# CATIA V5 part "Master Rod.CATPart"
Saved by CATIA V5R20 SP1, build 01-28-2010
Part number: Master Rod
Bounding box of the stored display mesh (mm): x -55.99 to 55.99, y -51.999 to 267.322, z -35 to 35
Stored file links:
  D:\v5_r20\psrt_files_downloaded\c13-catia-v5r20-prt\c13-catia-v5r20-figr-13-41\Part & Asm files\Master Rod.CATPart
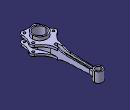
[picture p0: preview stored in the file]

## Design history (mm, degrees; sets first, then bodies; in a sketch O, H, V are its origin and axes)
Body1 (main body)
  Sketch1 on xy-plane, origin (0, 0, 0), H (1, 0, 0), V (0, 1, 0)
    arc A1 centre (0, 0) radius 31.5 from (-26.3425, 17.272) to (26.3425, 17.272) ccw
    arc A2 centre (0, 250) radius 17.5 from (14.7398, 240.5666) to (-14.7398, 240.5666) ccw
    point P1 (0, 250)
    line L1 (9, 220) -> (13, 60)
    point P2 (9, 220)
    point P3 (13, 60)
    arc A3 centre (94.6219, 62.0405) radius 81.6474 from (13, 60) to (26.3425, 17.272) ccw
    point P5 (26.3425, 17.272)
    arc A4 centre (45.4514, 220.9113) radius 36.4628 from (9, 220) to (14.7398, 240.5666) cw
    point P7 (14.7398, 240.5666)
    point P8 (-14.7398, 240.5666)
    point P9 (-9, 220)
    arc A5 centre (-45.4514, 220.9113) radius 36.4628 from (-9, 220) to (-14.7398, 240.5666) ccw
    point P11 (-13, 60)
    line L2 (-9, 220) -> (-13, 60)
    point P12 (-26.3425, 17.272)
    arc A6 centre (-94.6219, 62.0405) radius 81.6474 from (-13, 60) to (-26.3425, 17.272) cw
    radius A1 = 31.5
    radius A2 = 17.5
    distance P1 H = 250
    distance V P3 = 13
    distance P2 V = 9
    distance P1 P2 V = 30
    distance P3 P2 V = 160
    coincidence: P1 V
    tangency: A3 L1, A3 A1, A4 L1, A4 A2
    symmetry: P7 P8 V, P2 P9 V, A4 A5 V, P3 P11 V, L1 L2 V, P5 P12 V, A3 A6 V
  Pad1: profile Sketch1, direction (0, 0, 1), length 21, mirrored extent
  Sketch2 on face of Pad1, origin (0, 0, 21), H (1, 0, 0), V (0, 1, 0)
    point P1 (43, 16)
    point P2 (26, -39)
    arc A1 centre (43, 16) radius 13 from (53.3864, 8.1819) to (49.3111, 27.3653) ccw
    arc A2 centre (26, -39) radius 13 from (22.0235, -51.3769) to (38.9864, -38.4063) ccw
    reference projected line E1 (9, 220) -> (12.2872, 88.5122) from edge of Pad1
    arc A3 centre (84.2647, 90.3117) radius 72 from (49.3111, 27.3653) to (12.2872, 88.5122) cw
    point P5 (49.3111, 27.3653)
    point P6 (12.2872, 88.5122)
    arc A4 centre (110.9113, -35.118) radius 72 from (38.9864, -38.4063) to (53.3864, 8.1819) cw
    point P8 (38.9864, -38.4063)
    point P9 (53.3864, 8.1819)
    point P10 (-12.2872, 88.5122)
    point P11 (-49.3111, 27.3653)
    arc A5 centre (-84.2647, 90.3117) radius 72 from (-49.3111, 27.3653) to (-12.2872, 88.5122) ccw
    point P13 (-53.3864, 8.1819)
    arc A6 centre (-43, 16) radius 13 from (-53.3864, 8.1819) to (-49.3111, 27.3653) cw
    point P15 (-38.9864, -38.4063)
    arc A7 centre (-110.9113, -35.118) radius 72 from (-38.9864, -38.4063) to (-53.3864, 8.1819) ccw
    arc A8 centre (-26, -39) radius 13 from (-22.0235, -51.3769) to (-38.9864, -38.4063) cw
    line L1 (12.2872, 88.5122) -> (-12.2872, 88.5122)
    arc A9 centre (0, -119.9259) radius 72 from (-22.0235, -51.3769) to (22.0235, -51.3769) cw
    distance V P2 = 26
    distance P2 P1 H = 17
    distance P1 P2 V = 55
    distance P2 H = 39
    radius A1 = 13
    radius A2 = 13
    radius A3 = 72
    radius A4 = 72
    radius A9 = 72
    tangency: A3 E1, A3 A1, A4 A1, A4 A2, A9 A8, A9 A2
    symmetry: P6 P10 V, P5 P11 V, A3 A5 V, P9 P13 V, A1 A6 V, P8 P15 V, A4 A7 V, A2 A8 V
    horizontal: L1 H
  Pad2: profile Sketch2, direction (0, 0, -1), length 9
  Mirror1: of Pad2, Sketch2, about xy-plane
  Sketch3 on xy-plane, origin (0, 0, 0), H (1, 0, 0), V (0, 1, 0)
    circle A1 centre (0, 0) radius 31.5
    reference projected arc E1 centre (0, 0) radius 31.5 from (-26.3425, 17.272) to (26.3425, 17.272) ccw from edge of Pad2
    tangency: A1 E1
  Pad3: profile Sketch3, direction (0, 0, 1), length 35, mirrored extent
  Sketch4 on xy-plane, origin (0, 0, 0), H (1, 0, 0), V (0, 1, 0)
    circle A1 centre (0, 0) radius 26
    circle A2 centre (43, 16) radius 5
    circle A3 centre (26, -39) radius 5
    reference projected arc E1 centre (43, 16) radius 13 from (53.3864, 8.1819) to (49.3111, 27.3653) ccw from edge of Pad2
    reference projected arc E2 centre (26, -39) radius 13 from (22.0235, -51.3769) to (38.9864, -38.4063) ccw from edge of Pad2
    circle A4 centre (-26, -39) radius 5
    circle A5 centre (-43, 16) radius 5
    radius A1 = 26
    radius A3 = 5
    radius A2 = 5
    concentricity: A2 E1, A3 E2
    symmetry: A3 A4 V, A2 A5 V
  Pocket1: profile Sketch4, direction (0, 0, -1), length 35, mirrored extent
  Sketch5 on yz-plane, origin (0, 0, 0), H (0, 1, 0), V (0, 0, 1)
    line L1 (123.0834, 12) -> (250, 9)
    point P1 (123.0834, 12)
    point P2 (250, 9)
    arc A1 centre (124.9266, 89.9782) radius 78 from (88.5122, 21) to (123.0834, 12) ccw
    line L2 (88.5122, 21) -> (88.5122, 33.8539)
    line L3 (88.5122, 33.8539) -> (280.7471, 33.8539)
    line L4 (280.7471, 33.8539) -> (280.7471, 8.2732)
    point P8 (280.7471, 8.2732)
    line L5 (280.7471, 8.2732) -> (250, 9)
    distance P1 H = 12
    distance H P2 = 9
    distance V P2 = 250
    radius A1 = 78
    tangency: A1 L1, L5 A1
    vertical: L2 V, L4 V
    horizontal: L3 H
    coincidence: P8 L1
  Pocket2: profile Sketch5, direction (-1, 0, 0), length 35, mirrored extent
  Mirror2: of Pocket2, Sketch5, about xy-plane
  Sketch6 on xy-plane, origin (0, 0, 0), H (1, 0, 0), V (0, 1, 0)
    circle A1 centre (0, 250) radius 17.5
    point P1 (0, 250)
    reference projected arc E1 centre (0, 250) radius 17.5 from (17.5, 250) to (-17.5, 250) ccw from edge of Mirror2
    reference projected arc E2 centre (0, 250) radius 17.5 from (17.5, 250) to (-17.5, 250) ccw from edge of Mirror2
    coincidence: P1 V
    concentricity: E1 A1
    tangency: E2 A1
  Pad4: profile Sketch6, direction (0, 0, 1), length 21, mirrored extent
  Sketch7 on xy-plane, origin (0, 0, 0), H (1, 0, 0), V (0, 1, 0)
    circle A1 centre (0, 250) radius 12
    point P1 (0, 250)
    reference projected circle E1 centre (0, 250) radius 17.5 from edge of Pad4
    radius A1 = 12
    coincidence: P1 V
    concentricity: A1 E1
  Pocket3: profile Sketch7, direction (0, 0, -1), length 21, mirrored extent
  Sketch8 on xy-plane, origin (0, 0, 0), H (1, 0, 0), V (0, 1, 0)
    construction line L1 (0, 70) -> (0, 220)
    point P1 (0, 70)
    point P2 (0, 220)
    line L2 (-6, 70) -> (-6, 220)
    line L3 (6, 220) -> (6, 70)
    arc A1 centre (0, 220) radius 6 from (-6, 220) to (6, 220) cw
    arc A2 centre (0, 70) radius 6 from (6, 70) to (-6, 70) cw
    point P7 (0, 250)
    reference projected circle E1 centre (0, 250) radius 12 from edge of Pocket3
    length L1 = 150
    distance P7 P2 = 30
    radius A1 = 6
    coincidence: P1 V, P7 L1
    vertical: L1 V
    tangency: A1 L2, A2 L2, A1 L3, A2 L3
    parallelism: L1 L2
    concentricity: P7 E1
  Pocket4: profile Sketch8, direction (0, 0, 1), through (limit type 6), opposite side length -2.5
  Mirror3: of Pocket4, Sketch8, about xy-plane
